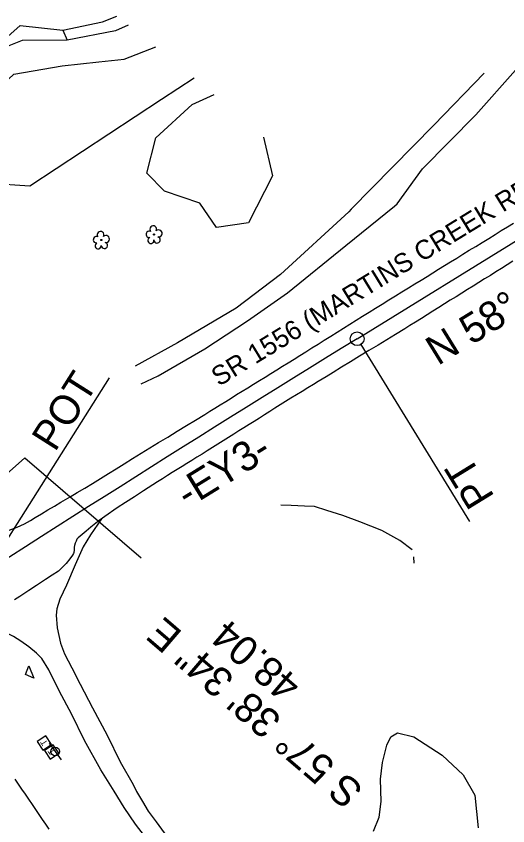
# Model space of a CAD drawing. Extents: x 478596 to 483012, y 490885 to 495165.
# Drawn here: x 480925.2 to 481192.2, y 493003.6 to 493443 of the extents above; entities that cross this region are included whole.
import ezdxf

# ---------------------------------------------------------------- set-up
doc = ezdxf.new("R2010")
doc.units = 0
for name, color, linetype in [('Exist Horizontal Alignment', 7, 'Continuous'), ('Exist Horizontal Alignment Direction Label', 7, 'Continuous'), ('Exist Other Culture Area Outline', 7, 'Continuous'), ('Exist Other Culture Sign', 7, 'Continuous'), ('Exist Roads EOP', 7, 'Continuous'), ('Exist Roads EOP Text', 7, 'Continuous'), ('Exist Roads Soil', 7, 'Continuous'), ('Exist Utilities Telephone Pedestal CELL', 7, 'Continuous'), ('Exist Utilities Telephone Pole CELL', 7, 'Continuous'), ('Exist Vegetation Hedge Row', 7, 'Continuous'), ('Exist Vegetation Tree CELL', 7, 'Continuous'), ('Exist Vegetation Woods Line', 7, 'Continuous')]:
    doc.layers.add(name, color=color, linetype=linetype)

msp = doc.modelspace()

# ---------------------------------------------------------------- linework, layer by layer
at = {"layer": 'Exist Horizontal Alignment'}
for p, q in [((481110.35, 493267.91), (481302.76, 493386.4)), ((481112.31, 493264.71), (481171.43, 493168.73)), ((480911.4, 493144.83), (480975.91, 493246.65))]:
    msp.add_line(p, q, dxfattribs=at)
msp.add_circle((481110.35, 493267.91), 3.75, dxfattribs=at)
for centre, radius, start, end in [((488084.67, 481943.17), 13300.03, 121.626761, 123.021402), ((480394.24, 492639.96), 634.61, 22.51531, 56.41358)]:
    msp.add_arc(centre, radius, start, end, dxfattribs=at)
at = {"layer": 'Exist Horizontal Alignment Direction Label'}
msp.add_lwpolyline([(480881.69, 493160.66), (480929.89, 493203.3), (480993.05, 493148.93)], dxfattribs=at)
at = {"layer": 'Exist Other Culture Area Outline'}
msp.add_line((481141.29, 493146.07), (481141.13, 493149.51), dxfattribs=at)
msp.add_lwpolyline([(481140.22, 493153.4), (481133.5, 493158.49), (481123.69, 493163.91), (481111.75, 493168.45), (481102.54, 493171.96), (481093.95, 493174.62), (481087.2, 493176.83), (481081.84, 493177.11), (481074.48, 493177.48), (481068.99, 493177.59)], dxfattribs=at)
at = {"layer": 'Exist Other Culture Sign'}
for p, q in [((480930.22, 493085.64), (480931.99, 493090.42)), ((480931.99, 493090.42), (480934.79, 493083.73)), ((480934.79, 493083.73), (480930.22, 493085.64))]:
    msp.add_line(p, q, dxfattribs=at)
at = {"layer": 'Exist Roads EOP'}
for points in [[(480921.34, 493164.1), (480925.78, 493165.57), (480929.66, 493167.47), (480932.92, 493169.33), (480935.51, 493170.88), (480938.91, 493172.93), (480942.44, 493175.04), (480945.98, 493177.13), (480949.39, 493179.13), (480954.5, 493182.15), (480958.38, 493184.45), (480962.52, 493186.9), (480966.73, 493189.42), (480970.99, 493192.02), (480975.27, 493194.69), (480979.58, 493197.39), (480983.93, 493200.1), (480988.4, 493202.87), (480993.05, 493205.73), (480997.8, 493208.66), (481002.58, 493211.59), (481007.47, 493214.58), (481012.57, 493217.66), (481017.68, 493220.75), (481022.62, 493223.77), (481027.68, 493226.88), (481030.37, 493228.55), (481033.17, 493230.29), (481036.05, 493232.07), (481038.97, 493233.88), (481041.93, 493235.71), (481044.94, 493237.57), (481047.98, 493239.45), (481051.05, 493241.35), (481054.15, 493243.26), (481057.28, 493245.19), (481060.42, 493247.13), (481063.55, 493249.07), (481066.67, 493251.01), (481069.78, 493252.94), (481072.91, 493254.89), (481076.08, 493256.86), (481079.27, 493258.85), (481082.5, 493260.88), (481085.78, 493262.93), (481089.12, 493265.02), (481092.53, 493267.14), (481095.99, 493269.3), (481099.48, 493271.47), (481102.96, 493273.64), (481106.42, 493275.8), (481109.88, 493277.95), (481113.36, 493280.1), (481116.87, 493282.28), (481120.41, 493284.49), (481123.99, 493286.72), (481127.58, 493288.94), (481131.15, 493291.16), (481134.7, 493293.35), (481138.23, 493295.53), (481141.7, 493297.67), (481145.07, 493299.75), (481148.33, 493301.77), (481151.49, 493303.72), (481154.63, 493305.67), (481157.84, 493307.65), (481161.11, 493309.66), (481164.45, 493311.71), (481167.85, 493313.79), (481171.29, 493315.9), (481174.78, 493318.04), (481178.32, 493320.21), (481181.84, 493322.38), (481185.29, 493324.5), (481188.65, 493326.58), (481191.95, 493328.62), (481195.23, 493330.65)], [(481195, 493309.94), (481191.91, 493308.01), (481188.84, 493306.09), (481185.77, 493304.18), (481182.7, 493302.27), (481179.62, 493300.36), (481176.53, 493298.45), (481173.43, 493296.53), (481170.32, 493294.6), (481167.2, 493292.67), (481164.07, 493290.72), (481160.94, 493288.77), (481157.81, 493286.82), (481154.66, 493284.85), (481151.52, 493282.88), (481148.38, 493280.92), (481145.24, 493278.95), (481142.1, 493276.99), (481139.06, 493275.09), (481136.24, 493273.34), (481131.23, 493270.24), (481126.56, 493267.4), (481121.72, 493264.49), (481116.75, 493261.51), (481111.71, 493258.47), (481106.71, 493255.43), (481101.87, 493252.44), (481097.41, 493249.67), (481093.52, 493247.29), (481089.25, 493244.68), (481086.6, 493243.07), (481083.62, 493241.25), (481080.5, 493239.35), (481077.44, 493237.47), (481074.44, 493235.63), (481071.49, 493233.81), (481068.59, 493232.01), (481065.72, 493230.21), (481062.87, 493228.42), (481060.06, 493226.62), (481057.26, 493224.84), (481054.47, 493223.07), (481051.69, 493221.32), (481048.92, 493219.58), (481046.14, 493217.84), (481043.33, 493216.08), (481040.48, 493214.29), (481037.6, 493212.49), (481034.71, 493210.67), (481031.84, 493208.88), (481029, 493207.1), (481026.18, 493205.33), (481023.39, 493203.58), (481020.64, 493201.87), (481017.93, 493200.2), (481015.26, 493198.56), (481012.62, 493196.92), (481009.97, 493195.28), (481007.32, 493193.61), (481004.66, 493191.94), (481002.03, 493190.27), (480999.45, 493188.61), (480994.4, 493185.37), (480989.47, 493182.17), (480984.57, 493178.98), (480980.12, 493176.08), (480978.23, 493174.83), (480975.07, 493172.72), (480970.2, 493169.27), (480965.73, 493165.62), (480963.2, 493163.52), (480958.87, 493159.89), (480958.47, 493159.46), (480958.22, 493159.09), (480957.7, 493158.12), (480957.19, 493156.9), (480956.85, 493155.75), (480956.69, 493154.74), (480956.65, 493153.89), (480956.68, 493152.86), (480956.65, 493152.56), (480956.6, 493152.27), (480956.52, 493151.98), (480956.24, 493151.3), (480955.81, 493150.49), (480954.38, 493148.42), (480952.38, 493145.99), (480948.11, 493141.83), (480944.75, 493139.6), (480941.21, 493137.3), (480936.3, 493134.07), (480932.04, 493131.27), (480927.12, 493128.09), (480924.26, 493126.23)], [(480924.44, 493028.86), (480926.24, 493026.25), (480928.11, 493023.54), (480930, 493020.8), (480931.89, 493018.02), (480933.8, 493015.21), (480935.7, 493012.41), (480937.55, 493009.67), (480939.37, 493007), (480941.15, 493004.38), (480942.96, 493001.71)]]:
    msp.add_lwpolyline(points, dxfattribs=at)
at = {"layer": 'Exist Roads Soil'}
for points in [[(480971.5, 493170.14), (480965.63, 493161.57), (480961.54, 493154.98), (480957.28, 493145.21), (480952.47, 493134.2), (480948.97, 493126.58), (480947.29, 493121.3), (480947, 493117.95), (480947.38, 493110.99), (480949.22, 493102.74), (480951.45, 493096.98), (480955.45, 493089.3), (480960, 493080.36), (480966.59, 493067.55), (480974.67, 493052.68), (480981.74, 493038.25), (480988.72, 493025.97), (480990.54, 493022.23), (480993.77, 493016.75), (480996.94, 493011.59), (481001.23, 493005.66), (481006.93, 492997.76)], [(480998, 492994.13), (480990.09, 493004.5), (480983.8, 493013.53), (480978.48, 493022.43), (480971.22, 493033.88), (480962.36, 493049.94), (480955.25, 493064.31), (480948.78, 493076.48), (480942.89, 493088.29), (480939.18, 493094.32), (480936.19, 493097.32), (480932.09, 493100.75), (480927.73, 493103.82), (480923.76, 493106.25), (480918.57, 493108.9), (480912.88, 493109.87), (480909.09, 493109.29), (480906.23, 493108.61), (480901.36, 493108.13)], [(481119.19, 493000.59), (481122.35, 493008.26), (481123.41, 493016.7), (481123.04, 493028.8), (481124.08, 493037.95), (481126.47, 493047.33), (481128.67, 493051.8), (481132.27, 493053.94), (481141.18, 493051.81), (481156.47, 493041.82), (481167.92, 493031.23), (481174.35, 493020.15), (481176.11, 493002.45)]]:
    msp.add_lwpolyline(points, dxfattribs=at)
at = {"layer": 'Exist Utilities Telephone Pedestal CELL'}
for p, q in [((480940.45, 493048.46), (480940.45, 493048.46)), ((480944.51, 493043.61), (480944.51, 493043.61))]:
    msp.add_line(p, q, dxfattribs=at)
for points in [[(480944.3, 493047.7), (480941.28, 493052.41), (480936.57, 493049.38), (480939.6, 493044.68), (480944.3, 493047.7)], [(480948.38, 493042.92), (480945.25, 493047.57), (480940.61, 493044.44), (480943.73, 493039.8), (480948.38, 493042.92)]]:
    msp.add_lwpolyline(points, dxfattribs=at)
at = {"layer": 'Exist Utilities Telephone Pole CELL'}
for p, q in [((480943.06, 493048.47), (480949.72, 493039.3)), ((480946.4, 493043.88), (480946.4, 493043.88))]:
    msp.add_line(p, q, dxfattribs=at)
msp.add_circle((480946.4, 493043.88), 2.41, dxfattribs=at)
at = {"layer": 'Exist Vegetation Hedge Row'}
for points in [[(480950.62, 493435.4), (480972.02, 493439.84), (480979.82, 493442.97)], [(480986.09, 493438.07), (480979.15, 493435.06), (480952.91, 493429.92)], [(481132.08, 493341.18), (481145.94, 493360.08), (481174.9, 493389.4), (481196.39, 493413.68), (481220.33, 493436.62), (481221.43, 493438.24)], [(481179.32, 493412.09), (481151.98, 493383.82), (481107.19, 493338.18)], [(480993, 493243.49), (481002.23, 493247.73), (481027.57, 493262.47), (481050.87, 493277.68), (481072.55, 493292.82), (481104.29, 493318.47), (481130.73, 493339.82), (481132.08, 493341.18)], [(481107.19, 493338.18), (481105.83, 493336.84), (481068.78, 493302.8), (481044.66, 493284.56), (481012.78, 493265.65), (480989.8, 493252.95)]]:
    msp.add_lwpolyline(points, dxfattribs=at)
at = {"layer": 'Exist Vegetation Tree CELL'}
for p, q in [((481000.04, 493324.45), (481000.04, 493324.45)), ((480971.41, 493321.47), (480971.41, 493321.47))]:
    msp.add_line(p, q, dxfattribs=at)
for centre in [(481000.04, 493324.45), (480971.41, 493321.47)]:
    msp.add_circle(centre, 0.326, dxfattribs=at)
for centre, radius, start, end in [((480999.65, 493327.32), 1.86, 330.1651, 219.7134), ((481002.59, 493325.04), 1.9, 257.1011, 134.1999), ((480968.81, 493321.62), 1.73, 62.6636, 279.3457), ((480971.03, 493324.34), 1.86, 330.1651, 219.7134), ((480973.96, 493322.06), 1.9, 257.1011, 134.1999), ((480997.43, 493324.6), 1.73, 62.6636, 279.3457), ((480998.34, 493321.33), 1.69, 111.5671, 6.231), ((481001.71, 493321.55), 1.7, 181.2822, 74.56), ((480969.71, 493318.35), 1.69, 111.5671, 6.231), ((480973.09, 493318.57), 1.7, 181.2822, 74.56)]:
    msp.add_arc(centre, radius, start, end, dxfattribs=at)
at = {"layer": 'Exist Vegetation Woods Line'}
for points in [[(480907.18, 493420.06), (480927.4, 493437.96), (480950.62, 493435.4)], [(480950.62, 493435.4), (480952.91, 493429.92)], [(480952.91, 493429.92), (480928.43, 493429.7), (480917.59, 493425.5), (480907.18, 493420.06)], [(480950.12, 493416.08), (480970.17, 493418.12), (480983.93, 493419.61), (481001.07, 493426.37)], [(480826.21, 493340.23), (480849.54, 493349.52), (480877.59, 493362.64), (480894.01, 493377.35), (480904.54, 493393.67), (480924, 493411.46), (480950.12, 493416.08)], [(481021.85, 493409.36), (481004.11, 493397.69), (480932.64, 493350.72), (480910.86, 493352.18), (480912.3, 493369.62), (480906.49, 493376.18), (480879.32, 493349.28)], [(481051.43, 493330.76), (481033.96, 493328.2), (481024.96, 493341.43), (481005.76, 493348.03), (480996.19, 493357.76), (481001.05, 493376.89), (481020.72, 493395), (481032.68, 493400.43)], [(481059.45, 493377.25), (481064.4, 493356.27), (481051.43, 493330.76)]]:
    msp.add_lwpolyline(points, dxfattribs=at)

# ---------------------------------------------------------------- texts
at = {"layer": 'Exist Horizontal Alignment'}
for s, rotation, p in [('POT', 57.6429, (480946.3, 493206.04)), ('PT', 121.6268, (481185.28, 493182.18))]:
    msp.add_text(s, height=16, rotation=rotation, dxfattribs=at).set_placement(p)
at = {"layer": 'Exist Horizontal Alignment Direction Label'}
for s, rotation, p in [('N 58%%d 22\' 24" E', 31.6268, (481154.21, 493253.04)), ('-EY3-', 31.6268, (481018.31, 493175.66)), ('S 57%%d 38\' 34" E', 139.3794, (481114.59, 493023.89)), ('48.04', 139.3794, (481080.94, 493081.53))]:
    msp.add_text(s, height=16, rotation=rotation, dxfattribs=at).set_placement(p)
at = {"layer": 'Exist Roads EOP Text'}
msp.add_text('SR 1556 (MARTINS CREEK RD)', height=10.4, rotation=31.5156, dxfattribs=at).set_placement((481035.31, 493241.79))
at = {"layer": 'Exist Utilities Telephone Pedestal CELL'}
for rotation, p in [(122.6971, (480942.51, 493048.44)), (123.923, (480946.56, 493043.63))]:
    msp.add_text('T', height=3.42, rotation=rotation, dxfattribs=at).set_placement(p)

doc.saveas('drawing.dxf')
